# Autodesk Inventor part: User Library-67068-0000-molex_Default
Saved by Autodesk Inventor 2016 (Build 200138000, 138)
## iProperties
Created: 2012-01
Part Number: User Library-67068-0000-molex_Default
Document SubType Name: Modeling
Designer: Trevor
Density: 1 g/cm^3
Material: Generic
Appearance: Default
Author: Trevor
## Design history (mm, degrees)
feature "Base1"
node "Mirror17"
